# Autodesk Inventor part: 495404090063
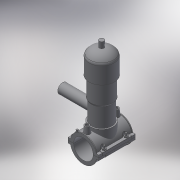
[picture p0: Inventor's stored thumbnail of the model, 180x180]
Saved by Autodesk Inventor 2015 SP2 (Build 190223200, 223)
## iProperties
Created: 2017-07
Part Number: 495404090063
Material: Generic
Description: PLASSON TAPPING VALVE 90-63
Document SubType Name: Modeling
Designer: KIM
Density: 1 g/cm^3
Appearance: Default
Author: KIM
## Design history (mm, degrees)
derived "495404-4954S4.ipt"
feature "Solid1::495404-4954S4.ipt"
feature "Solid2::495404-4954S4.ipt"
tag "TaggingFeature1"
body "Solid1"
body "Solid2"
other parameters: "d2" = 126, "d3" = 22.5, "d4" = 118, "d5" = 0, "d6" = 0.1, "d8" = 0, "d19" = 6, "d20" = 6, "d21" = 70.8, "d23" = 0, "d24" = 35.4, "d26" = 0, "d27" = 3, "d28" = 3, "d29" = 3, "d31" = 6, "d32" = 0, "d33" = 0, "d34" = 0.6, "d40" = 60.84, "d47" = 109.5, "d70" = 15, "d72" = 0, "d73" = 6, "d75" = 5, "d76" = 0, "d77" = 4.5, "d78" = 75, "d79" = 15, "d80" = 47.2, "d82" = 5 deg, "d84" = 4, "d85" = 14, "d86" = 0, "d87" = 3, "d88" = 0, "d89" = 1, "d90" = 1, "d91" = 94.4, "d92" = 0, "d93" = 0.5, "d94" = 47.36842, "d96" = 120.51, "d97" = 2.36, "d98" = 0, "d120" = 140 deg, "d121" = 24.228, "d122" = 20 deg, "d123" = 234, "d124" = 70.2, "d126" = 0, "d143" = 92.7, "d145" = 20.76923, "d149" = 1.35, "d150" = 22.84615, "d153" = 118, "d154" = 0, "d156" = 58.5, "d157" = 160 deg, "d159" = 5.4, "d161" = 1.35, "d162" = 70.8, "d163" = 0, "d164" = 45, "d167" = 9, "d168" = 57.07317, "d170" = 3, "d172" = 0, "d173" = 1, "d175" = 45, "d176" = 20 deg, "d177" = 6.3, "d178" = 27, "d180" = 0, "d183" = 10.8, "d184" = 5.04, "d185" = 38.35, "d186" = 38.35, "d187" = 58.5, "d188" = 8.1, "d189" = 6.3, "d190" = 0, "d191" = 87.75, "d193" = 6.8, "d194" = 2.95, "d195" = 90 deg, "d197" = 0, "d199" = 0, "d205" = 14.64, "d206" = 81.33333, "d207" = 244, "d208" = 224.48, "d209" = 207.4, "d210" = 200.08, "d211" = 146.4, "d212" = 85.4, "d213" = 65.88, "d214" = 73.2, "d216" = 19.52, "d217" = 70.76, "d218" = 80.52, "d222" = 0, "d223" = 117, "d224" = 186, "d225" = 51, "d226" = 63, "d229" = 186, "d230" = 0, "B_" = 126, "H_" = 186, "L_" = 118, "d_t" = 6, "d_1" = 63, "H_1" = 51, "H_2" = 244, "d148" = 1.35, "d160" = 1.35, "d169" = 3, "d192" = 6.8, "d228" = 50.4
